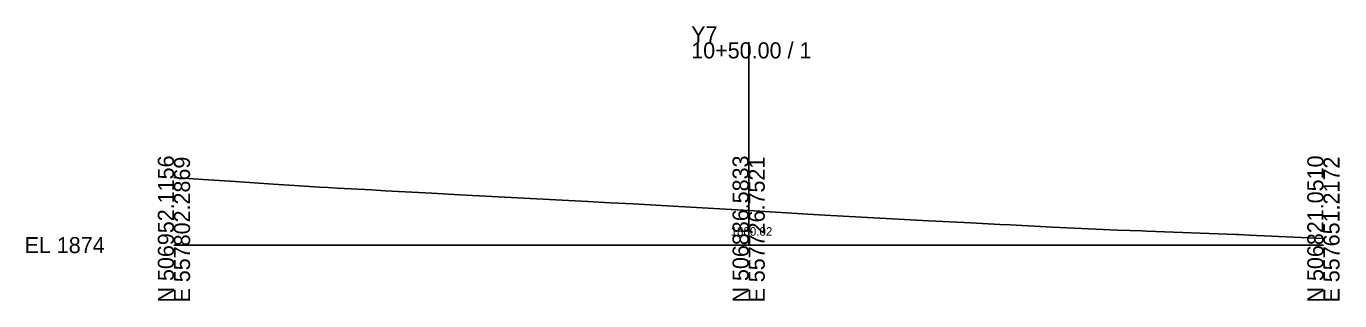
# Model space of a CAD drawing. Extents: x -26 to 557959, y -10 to 506992.
# Drawn here: x -25.7 to 202.8, y 490.3 to 538.1 of the extents above; entities that cross this region are included whole.
import ezdxf

# ---------------------------------------------------------------- set-up
doc = ezdxf.new("R2010")
doc.units = 0
for name, color, linetype in [('Default', 7, 'Continuous'), ('Exist Cross Section Cell', 7, 'Continuous'), ('Exist XS Center Line Elevation Label', 7, 'Continuous'), ('Exist XS Ground Line', 7, 'Continuous')]:
    doc.layers.add(name, color=color, linetype=linetype)

msp = doc.modelspace()

# ---------------------------------------------------------------- linework, layer by layer
at = {"layer": 'Exist Cross Section Cell'}
for p, q in [((100, 500), (100, 535.32)), ((0, 500), (100, 500)), ((100, 500), (200, 500))]:
    msp.add_line(p, q, dxfattribs=at)
at = {"layer": 'Exist XS Ground Line'}
for p, q in [((0, 511.77), (5.09, 511.43)), ((5.09, 511.43), (10.66, 511.05)), ((10.66, 511.05), (17.26, 510.61)), ((17.26, 510.61), (20.97, 510.38)), ((20.97, 510.38), (25.34, 510.11)), ((25.34, 510.11), (26.83, 510.03)), ((26.83, 510.03), (28.38, 509.94)), ((28.38, 509.94), (34.42, 509.6)), ((34.42, 509.6), (36.73, 509.47)), ((36.73, 509.47), (44.9, 509.03)), ((44.9, 509.03), (49.76, 508.76)), ((49.76, 508.76), (72.03, 507.58)), ((72.03, 507.58), (75.91, 507.37)), ((75.91, 507.37), (79.89, 507.17)), ((79.89, 507.17), (84.86, 506.92)), ((84.86, 506.92), (100, 506.02)), ((100, 506.02), (110.29, 505.4)), ((110.29, 505.4), (113.27, 505.23)), ((113.27, 505.23), (131.35, 504.22)), ((131.35, 504.22), (138.66, 503.89)), ((138.66, 503.89), (143.69, 503.61)), ((143.69, 503.61), (145.5, 503.52)), ((145.5, 503.52), (152.84, 503.12)), ((152.84, 503.12), (164.17, 502.61)), ((164.17, 502.61), (168.47, 502.46)), ((168.47, 502.46), (169.3, 502.44)), ((169.3, 502.44), (184.76, 501.84)), ((184.76, 501.84), (185.28, 501.82)), ((185.28, 501.82), (187.06, 501.73)), ((187.06, 501.73), (200, 501.15))]:
    msp.add_line(p, q, dxfattribs=at)

# ---------------------------------------------------------------- texts
at = {"layer": 'Default'}
msp.add_text('-', height=0.0001, dxfattribs=at).set_placement((0, 500))
at = {"layer": 'Exist Cross Section Cell'}
for s, p in [('Y7', (90, 535.32)), ('10+50.00 / 1', (90, 532.52)), ('EL 1874', (-26, 498.6))]:
    msp.add_text(s, height=2.8, dxfattribs=at).set_placement(p)
for s, p in [('N 506952.1156', (0, 490)), ('E 557802.2869', (2.8, 490)), ('N 506886.5833', (100, 490)), ('E 557726.7521', (102.8, 490)), ('N 506821.0510', (200, 490)), ('E 557651.2172', (202.8, 490))]:
    msp.add_text(s, height=2.8, rotation=90, dxfattribs=at).set_placement(p)
at = {"layer": 'Exist XS Center Line Elevation Label'}
msp.add_text('1880.02', height=1.5, dxfattribs=at).set_placement((96.86, 501.63))

doc.saveas('drawing.dxf')
